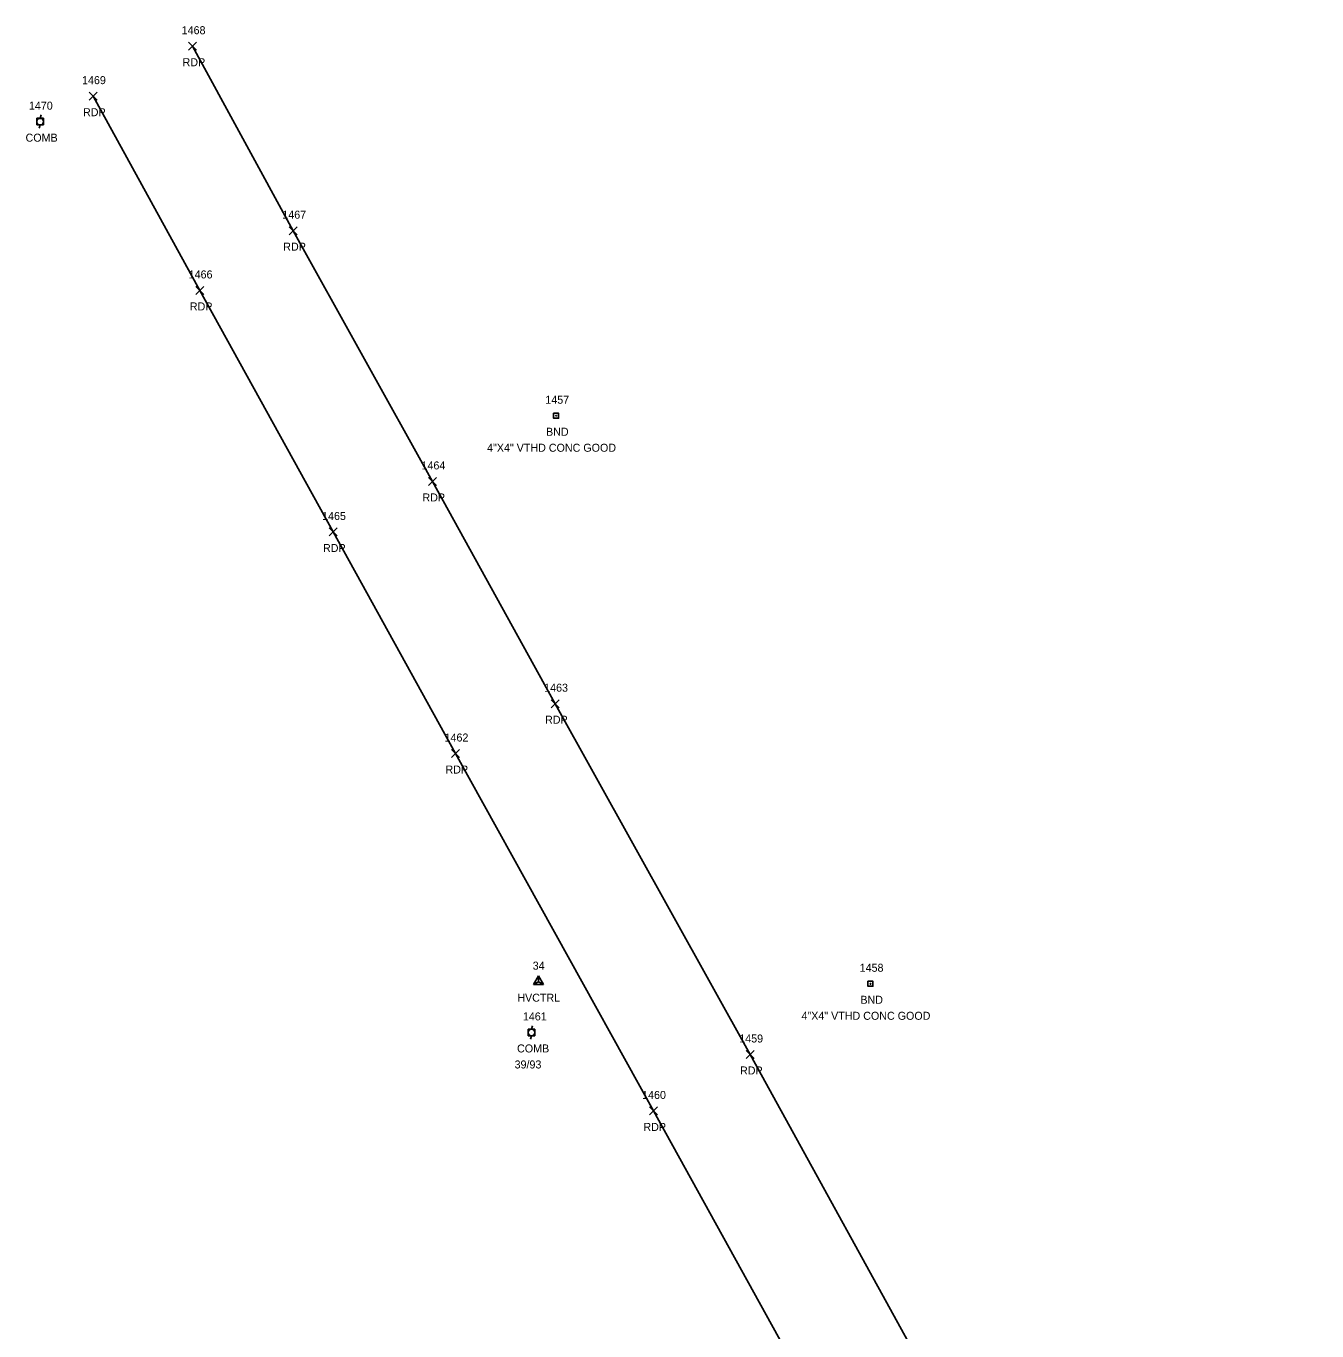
# Model space of a CAD drawing. Extents: x 1496556 to 1498241, y 599216 to 604470.
# Drawn here: x 1496555.6 to 1496878.1, y 603954.5 to 604280.5 of the extents above; entities that cross this region are included whole.
import ezdxf

# ---------------------------------------------------------------- set-up
doc = ezdxf.new("R2010")
doc.units = 0
for name, color, linetype in [('C_A', 7, 'Continuous'), ('C_I', 7, 'Continuous'), ('CPSM', 7, 'Continuous'), ('Level 18', 7, 'Continuous'), ('M_A', 7, 'Continuous'), ('M_C', 7, 'Continuous'), ('M_I', 7, 'Continuous'), ('P_A', 7, 'Continuous'), ('P_I', 7, 'Continuous'), ('P_TIC', 7, 'Continuous'), ('PET', 7, 'Continuous'), ('U_A', 7, 'Continuous'), ('U_C', 7, 'Continuous'), ('U_I', 7, 'Continuous'), ('UP', 7, 'Continuous')]:
    doc.layers.add(name, color=color, linetype=linetype)

msp = doc.modelspace()

# ---------------------------------------------------------------- linework, layer by layer
at = {"layer": 'CPSM'}
for p, q in [((1496682.37, 604041), (1496683.62, 604043.16)), ((1496682.37, 604041), (1496683.62, 604041.72)), ((1496682.37, 604041), (1496684.87, 604041)), ((1496684.87, 604041), (1496683.62, 604043.16)), ((1496683.62, 604041.72), (1496683.62, 604043.16)), ((1496683.62, 604041.72), (1496683.62, 604041.72)), ((1496683.62, 604041.72), (1496684.87, 604041))]:
    msp.add_line(p, q, dxfattribs=at)
at = {"layer": 'Level 18'}
for points in [[(1496687.39, 604183.76), (1496688.64, 604183.76), (1496688.64, 604182.51), (1496687.39, 604182.51)], [(1496765.91, 604041.82), (1496767.16, 604041.82), (1496767.16, 604040.57), (1496765.91, 604040.57)]]:
    msp.add_lwpolyline(points, close=True, dxfattribs=at)
for centre in [(1496688.01, 604183.14), (1496766.53, 604041.2)]:
    msp.add_circle(centre, 0.0833, dxfattribs=at)
at = {"layer": 'P_TIC'}
for points in [[(1496596.22, 604274.47), (1496598.22, 604276.47)], [(1496598.22, 604274.47), (1496596.22, 604276.47)], [(1496571.34, 604261.99), (1496573.34, 604263.99)], [(1496573.34, 604261.99), (1496571.34, 604263.99)], [(1496621.36, 604228.38), (1496623.36, 604230.38)], [(1496623.36, 604228.38), (1496621.36, 604230.38)], [(1496598.03, 604213.45), (1496600.03, 604215.45)], [(1496600.03, 604213.45), (1496598.03, 604215.45)], [(1496656.13, 604165.72), (1496658.13, 604167.72)], [(1496658.13, 604165.72), (1496656.13, 604167.72)], [(1496631.3, 604153.09), (1496633.3, 604155.09)], [(1496633.3, 604153.09), (1496631.3, 604155.09)], [(1496686.77, 604110.18), (1496688.77, 604112.18)], [(1496688.77, 604110.18), (1496686.77, 604112.18)], [(1496661.89, 604097.73), (1496663.89, 604099.73)], [(1496663.89, 604097.73), (1496661.89, 604099.73)], [(1496735.46, 604022.53), (1496737.46, 604024.53)], [(1496737.46, 604022.53), (1496735.46, 604024.53)], [(1496711.33, 604008.42), (1496713.33, 604010.42)], [(1496713.33, 604008.42), (1496711.33, 604010.42)]]:
    msp.add_lwpolyline(points, dxfattribs=at)
at = {"layer": 'PET'}
for points in [[(1497200.78, 603168.36), (1497190.31, 603189.95), (1497178.56, 603214.16), (1497156.38, 603259.17), (1497132.76, 603304.93), (1497107.74, 603351.81), (1497085.25, 603391.58), (1497052.51, 603451.39), (1497026.34, 603497.64), (1496978.11, 603585.44), (1496929.41, 603673.01), (1496891.52, 603741.51), (1496859.85, 603799.39), (1496832.17, 603849.95), (1496783.86, 603937.37), (1496736.46, 604023.53), (1496687.77, 604111.18), (1496657.13, 604166.72), (1496622.36, 604229.38), (1496597.22, 604275.47)], [(1497183.49, 603131.83), (1497176.45, 603149.42), (1497165.78, 603173.58), (1497153.07, 603202.24), (1497131.76, 603246.13), (1497108.09, 603291.8), (1497082.6, 603339.21), (1497060.69, 603378.6), (1497027.78, 603438.86), (1497002.63, 603483.06), (1496952.93, 603573.18), (1496904.09, 603661), (1496858.14, 603744.51), (1496836.02, 603785.33), (1496807.5, 603837.5), (1496759.38, 603924.22), (1496712.33, 604009.42), (1496662.89, 604098.73), (1496632.3, 604154.09), (1496599.03, 604214.45), (1496572.34, 604262.99)]]:
    msp.add_lwpolyline(points, dxfattribs=at)
at = {"layer": 'UP'}
for p, q in [((1496558.26, 604255.79), (1496558.26, 604257.46)), ((1496558.26, 604257.46), (1496559.93, 604257.46)), ((1496559.35, 604258.29), (1496559.1, 604257.46)), ((1496559.1, 604256.62), (1496559.1, 604256.62)), ((1496559.93, 604257.46), (1496559.93, 604255.79)), ((1496559.93, 604255.79), (1496558.26, 604255.79)), ((1496558.85, 604254.96), (1496559.1, 604255.79)), ((1496681.05, 604028.2), (1496681.05, 604029.87)), ((1496681.05, 604029.87), (1496682.71, 604029.87)), ((1496682.71, 604028.2), (1496681.05, 604028.2)), ((1496681.63, 604027.37), (1496681.88, 604028.2)), ((1496682.13, 604030.7), (1496681.88, 604029.87)), ((1496681.88, 604029.04), (1496681.88, 604029.04)), ((1496682.71, 604029.87), (1496682.71, 604028.2))]:
    msp.add_line(p, q, dxfattribs=at)
for centre in [(1496559.1, 604256.62), (1496681.88, 604029.04)]:
    msp.add_circle(centre, 0.833, dxfattribs=at)

# ---------------------------------------------------------------- texts
at = {"layer": 'C_A'}
msp.add_text('HVCTRL', height=2, dxfattribs=at).set_placement((1496678.32, 604036.72))
at = {"layer": 'C_I'}
msp.add_text('34', height=2, dxfattribs=at).set_placement((1496682.16, 604044.72))
at = {"layer": 'M_A'}
for p in [(1496685.5, 604178.14), (1496764.02, 604036.2)]:
    msp.add_text('BND', height=2, dxfattribs=at).set_placement(p)
at = {"layer": 'M_C'}
for p in [(1496670.77, 604174.14), (1496749.3, 604032.2)]:
    msp.add_text('4"X4" VTHD CONC GOOD', height=2, dxfattribs=at).set_placement(p)
at = {"layer": 'M_I'}
for s, p in [('1457', (1496685.32, 604186.14)), ('1458', (1496763.84, 604044.2))]:
    msp.add_text(s, height=2, dxfattribs=at).set_placement(p)
at = {"layer": 'P_A'}
for p in [(1496594.71, 604270.47), (1496569.83, 604257.99), (1496619.85, 604224.38), (1496596.52, 604209.45), (1496654.62, 604161.72), (1496629.78, 604149.09), (1496685.25, 604106.18), (1496660.38, 604093.73), (1496733.95, 604018.53), (1496709.82, 604004.42)]:
    msp.add_text('RDP', height=2, dxfattribs=at).set_placement(p)
at = {"layer": 'P_I'}
for s, p in [('1468', (1496594.48, 604278.47)), ('1469', (1496569.59, 604265.99)), ('1467', (1496619.62, 604232.38)), ('1466', (1496596.23, 604217.45)), ('1464', (1496654.39, 604169.72)), ('1465', (1496629.56, 604157.09)), ('1463', (1496685.03, 604114.18)), ('1462', (1496660.15, 604101.73)), ('1459', (1496733.76, 604026.53)), ('1460', (1496709.5, 604012.42))]:
    msp.add_text(s, height=2, dxfattribs=at).set_placement(p)
at = {"layer": 'U_A'}
for p in [(1496555.48, 604251.62), (1496678.26, 604024.04)]:
    msp.add_text('COMB', height=2, dxfattribs=at).set_placement(p)
at = {"layer": 'U_C'}
msp.add_text('39/93', height=2, dxfattribs=at).set_placement((1496677.64, 604020.04))
at = {"layer": 'U_I'}
for s, p in [('1470', (1496556.32, 604259.62)), ('1461', (1496679.71, 604032.04))]:
    msp.add_text(s, height=2, dxfattribs=at).set_placement(p)

doc.saveas('drawing.dxf')
